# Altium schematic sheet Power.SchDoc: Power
size A4; DocumentNumber: MB1167; Revision: B.1; SheetNumber: 3; SheetTotal: 17; Project: STM327x6G-EVAL
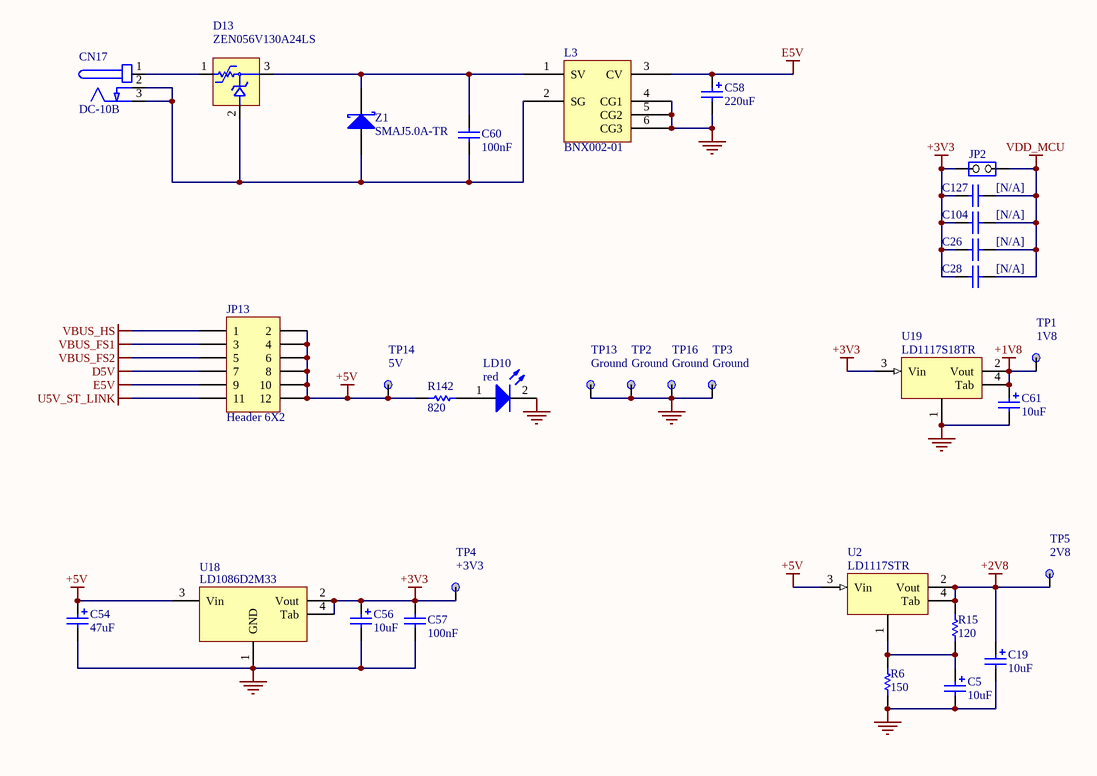
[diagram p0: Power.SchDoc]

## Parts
C5  10uF  [TAN-A]
C19  10uF  [TAN-A]
C26  [N/A]  [0603C]
C28  [N/A]  [0603C]
C54  47uF  [CAE_5R3X5R3_H5R4]
C56  10uF  [TAN-A]
C57  100nF  [0603C]
C58  220uF  [c310m-6]
C60  100nF  [0603C]
C61  10uF  [TAN-A]
C104  [N/A]  [0603C]
C127  [N/A]  [0603C]
CN17  DC-10B  [PWR_JACK_DC10]
D13  ZEN056V130A24LS  [TYCO_ZEN056V130A24LS]
JP2  (no value)  [SIP2]
JP13  Header 6X2  [HDR_2X6_2R54]
L3  BNX002-01  [BNX001]
LD10  red  [0603D]
R6  150  [0603R]
R15  120  [0603R]
R142  820  [0603R]
TP1  1V8  [TP]
TP2  Ground  [TP]
TP3  Ground  [TP]
TP4  +3V3  [TP]
TP5  2V8  [TP]
TP13  Ground  [TP]
TP14  5V  [TP]
TP16  Ground  [TP]
U2  LD1117STR  [SOT-223]
U18  LD1086D2M33  [TO263-3]
U19  LD1117S18TR  [SOT-223]
Z1  SMAJ5.0A-TR  [sma]

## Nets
+1V8: C61.1 TP1.1 U19.2(Vout) U19.4(Tab)
+2V8: C19.1 R15.1 TP5.1 U2.2(Vout) U2.4(Tab)
+3V3: C26.1 C28.1 C56.1 C57.1 C104.1 C127.1 JP2.1(COMMON) TP4.1 U18.2(Vout) U18.4(Tab) U19.3(Vin)
+5V: C54.1 JP13.2 JP13.4 JP13.6 JP13.8 JP13.10 JP13.12 R142.2 TP14.1 U2.3(Vin) U18.3(Vin)
D5V: JP13.7
E5V: C58.1 JP13.9 L3.3(CV)
GND: C5.2 C19.2 C54.2 C56.2 C57.2 C58.2 C61.2 L3.4(CG1) L3.5(CG2) L3.6(CG3) LD10.2(K) R6.2 TP2.1 TP3.1 TP13.1 TP16.1 U18.1(GND) U19.1
U5V_ST_LINK: JP13.11
VBUS_FS1: JP13.3
VBUS_FS2: JP13.5
VBUS_HS: JP13.1
VDD_MCU: C26.2 C28.2 C104.2 C127.2 JP2.2(NO)
NetC5_1: C5.1 R6.1 R15.2 U2.1
NetC60_1: C60.1 D13.3 L3.1(SV) Z1.2(K)
NetC60_2: C60.2 CN17.2(GND) CN17.3(GND) D13.2 L3.2(SG) Z1.1(A)
NetCN17_1: CN17.1(+) D13.1
NetLD10_1: LD10.1(A) R142.1

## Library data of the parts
C5 C19 C56 C61 = Cap Pol1: Polarized Capacitor (Radial)
C26 C28 C57 C104 C127 = Cap: Capacitor; Value: 10nF
C54 = Cap Pol1: Polarized Capacitor (Radial); Value: 10uF
C58 = Cap Pol1: Polarized Capacitor (Radial); Value: 47uF
C60 = CAP: Capacitor; Value: 100pF
CN17 = PJ202A
JP2 = JP2
JP13 = Header 6X2: Header, 6-Pin, Dual row
L3 = BNX002
LD10 = LED2: Typical RED, GREEN, YELLOW, AMBER GaAs LED
R6 R15 R142 = res1: Resistor; Value: 1K
TP1-TP5 TP13 TP14 TP16 = TP
U2 U19 = LD1117
U18 = VOLTREG1
Z1 = D Schottky: Schottky Diode; Code - JEDEC: DO-214-AA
